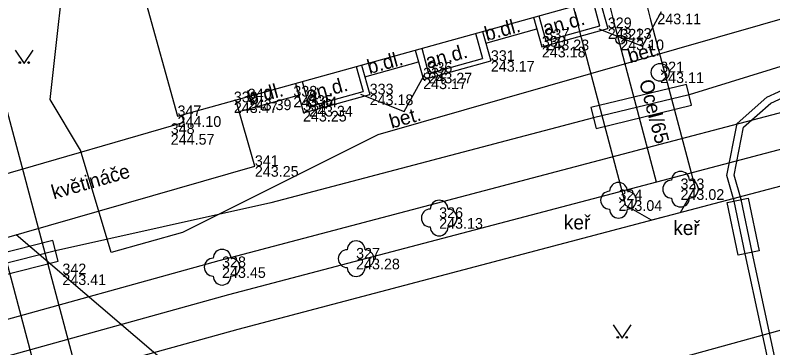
# Model space of a CAD drawing. Extents: x -599432 to -598680, y -1159407 to -1158632.
# Drawn here: x -599127.27 to -599106.02, y -1158908.05 to -1158898.71 of the extents above; entities that cross this region are included whole.
import ezdxf

# ---------------------------------------------------------------- set-up
doc = ezdxf.new("R2010")
doc.units = 0
for name, color, linetype in [('0004 VY - Body podrobné', 7, 'Continuous'), ('0005 VY - Body podrobné - čísla', 7, 'Continuous'), ('0006 VY - Body podrobné - výšky', 7, 'Continuous'), ('0007 ZA - Budova - zděná', 7, 'Continuous'), ('0025 ZA - Opěrná zeď', 7, 'Continuous'), ('0030 ZA - Chodník', 7, 'Continuous'), ('0031 ZA - Ostatní rozhraní', 7, 'Continuous'), ('0032 TE - Popis povrchu', 7, 'Continuous'), ('0034 ZA - Kultury - značky', 7, 'Continuous'), ('0035 ZA - Strom - značka', 7, 'Continuous'), ('0036 TE - Strom - popis', 7, 'Continuous'), ('0074 TE - Vysvětlivky', 7, 'Continuous'), ('0075 ZA - BVK - kanalizace - buňky', 7, 'Continuous'), ('0092 ZA - RWE - plynovod - buňky', 7, 'Continuous'), ('0116 PV - budova převzatá z mapy', 7, 'Continuous'), ('0254 PV - TB - horkovod - vedení', 7, 'Continuous'), ('0255 PV - TB - horkovod - okraj', 7, 'Continuous'), ('0264 PV - TB - parovod mimo provoz', 7, 'Continuous'), ('0301 PV - RWE - popis', 7, 'Continuous'), ('0302 PV - RWE - NTL', 7, 'Continuous'), ('0303 PV - RWE - NTL přípojka', 7, 'Continuous'), ('0308 PV - RWE - ochranné pásmo', 7, 'Continuous'), ('0354 PV - EON - VN', 7, 'Continuous'), ('0367 PV - EON - VN chránička', 7, 'Continuous'), ('0454 PV - PODA -  vedeni budoucnost', 7, 'Continuous'), ('0552 PV - NETBOX - vedení', 7, 'Continuous'), ('0553 PV - NETBOX - chranička', 7, 'Continuous')]:
    doc.layers.add(name, color=color, linetype=linetype)

msp = doc.modelspace()

# ---------------------------------------------------------------- linework, layer by layer
at = {"layer": '0004 VY - Body podrobné'}
for p, q in [((-599110.65, -1158899.08), (-599110.65, -1158899.08)), ((-599112.4, -1158899.4), (-599112.4, -1158899.4)), ((-599110.3, -1158899.4), (-599110.3, -1158899.4)), ((-599112.5, -1158899.6), (-599112.5, -1158899.6)), ((-599113.93, -1158900), (-599113.93, -1158900)), ((-599115.68, -1158900.33), (-599115.68, -1158900.33)), ((-599109.18, -1158900.32), (-599109.18, -1158900.32)), ((-599115.83, -1158900.49), (-599115.83, -1158900.49)), ((-599119.47, -1158901), (-599119.47, -1158901)), ((-599117.33, -1158900.94), (-599117.33, -1158900.94)), ((-599121.14, -1158901.16), (-599121.14, -1158901.16)), ((-599120.75, -1158901.08), (-599120.75, -1158901.08)), ((-599119.2, -1158901.4), (-599119.2, -1158901.4)), ((-599119.03, -1158901.26), (-599119.03, -1158901.26)), ((-599122.72, -1158901.55), (-599122.72, -1158901.55)), ((-599122.91, -1158902.05), (-599122.91, -1158902.05)), ((-599120.55, -1158902.95), (-599120.55, -1158902.95)), ((-599108.61, -1158903.6), (-599108.61, -1158903.6)), ((-599110.35, -1158903.91), (-599110.35, -1158903.91)), ((-599115.38, -1158904.41), (-599115.38, -1158904.41)), ((-599117.71, -1158905.55), (-599117.71, -1158905.55)), ((-599121.47, -1158905.79), (-599121.47, -1158905.79)), ((-599125.95, -1158905.99), (-599125.95, -1158905.99))]:
    msp.add_line(p, q, dxfattribs=at)
at = {"layer": '0007 ZA - Budova - zděná'}
msp.add_line((-599122.72, -1158901.55), (-599062.29, -1158884.74), dxfattribs=at)
at = {"layer": '0025 ZA - Opěrná zeď'}
for p, q in [((-599120.55, -1158902.95), (-599121.085, -1158901.095)), ((-599122.601, -1158901.517), (-599122.539, -1158901.732)), ((-599122.539, -1158901.732), (-599129.527, -1158903.746)), ((-599129.05, -1158905.4), (-599120.55, -1158902.95))]:
    msp.add_line(p, q, dxfattribs=at)
at = {"layer": '0030 ZA - Chodník'}
msp.add_line((-599116.59, -1158913.97), (-599127.25, -1158904.881), dxfattribs=at)
at = {"layer": '0031 ZA - Ostatní rozhraní'}
for p, q in [((-599110.879, -1158898.256), (-599110.649, -1158899.085)), ((-599111.074, -1158898.31), (-599110.878, -1158899.014)), ((-599112.731, -1158898.771), (-599112.5, -1158899.6)), ((-599112.586, -1158898.731), (-599112.39, -1158899.434)), ((-599114.07, -1158899.497), (-599112.639, -1158899.099)), ((-599112.5, -1158899.6), (-599110.649, -1158899.085)), ((-599112.39, -1158899.437), (-599110.877, -1158899.016)), ((-599114.358, -1158899.224), (-599114.162, -1158899.927)), ((-599114.161, -1158899.169), (-599113.931, -1158899.998)), ((-599116.051, -1158899.695), (-599115.821, -1158900.524)), ((-599115.871, -1158899.645), (-599115.675, -1158900.348)), ((-599115.674, -1158900.35), (-599114.162, -1158899.93)), ((-599117.708, -1158900.156), (-599117.512, -1158900.859)), ((-599117.56, -1158900.115), (-599117.329, -1158900.943)), ((-599117.469, -1158900.442), (-599115.96, -1158900.022)), ((-599115.821, -1158900.524), (-599113.931, -1158899.998)), ((-599119.22, -1158900.576), (-599119.024, -1158901.282)), ((-599119.414, -1158900.63), (-599119.184, -1158901.459)), ((-599120.991, -1158901.422), (-599119.323, -1158900.958)), ((-599119.184, -1158901.459), (-599117.329, -1158900.943)), ((-599119.024, -1158901.282), (-599117.511, -1158900.861))]:
    msp.add_line(p, q, dxfattribs=at)
at = {"layer": '0032 TE - Popis povrchu'}
for p, q in [((-599109.68, -1158899.585), (-599109.146, -1158898.614)), ((-599110.899, -1158899.097), (-599109.68, -1158899.585)), ((-599116.366, -1158901.421), (-599115.768, -1158900.335)), ((-599117.584, -1158900.933), (-599116.366, -1158901.421))]:
    msp.add_line(p, q, dxfattribs=at)
at = {"layer": '0034 ZA - Kultury - značky'}
for points in [[(-599127.271, -1158899.696), (-599127.021, -1158900.071), (-599126.771, -1158899.696)], [(-599110.495, -1158907.41), (-599110.245, -1158907.785), (-599109.995, -1158907.41)]]:
    msp.add_lwpolyline(points, dxfattribs=at)
for centre in [(-599127.146, -1158900.046), (-599126.896, -1158900.046), (-599110.37, -1158907.76), (-599110.12, -1158907.76)]:
    msp.add_circle(centre, 0.025, dxfattribs=at)
at = {"layer": '0035 ZA - Strom - značka'}
for centre in [(-599108.61, -1158903.6), (-599110.35, -1158903.91), (-599115.38, -1158904.41), (-599117.71, -1158905.55), (-599121.47, -1158905.79)]:
    msp.add_circle(centre, 0.00025, dxfattribs=at)
for centre, start, end in [((-599108.61, -1158903.35), 0, 180), ((-599108.86, -1158903.6), 90, 270), ((-599108.36, -1158903.6), 270, 90), ((-599110.35, -1158903.66), 0, 180), ((-599110.6, -1158903.91), 90, 270), ((-599110.1, -1158903.91), 270, 90), ((-599115.38, -1158904.16), 0, 180), ((-599108.61, -1158903.85), 180, 360), ((-599115.63, -1158904.41), 90, 270), ((-599115.13, -1158904.41), 270, 90), ((-599110.35, -1158904.16), 180, 360), ((-599115.38, -1158904.66), 180, 360), ((-599117.71, -1158905.3), 0, 180), ((-599121.47, -1158905.54), 0, 180), ((-599117.96, -1158905.55), 90, 270), ((-599117.46, -1158905.55), 270, 90), ((-599121.72, -1158905.79), 90, 270), ((-599121.22, -1158905.79), 270, 90), ((-599117.71, -1158905.8), 180, 360), ((-599121.47, -1158906.04), 180, 360)]:
    msp.add_arc(centre, 0.25, start, end, dxfattribs=at)
at = {"layer": '0075 ZA - BVK - kanalizace - buňky'}
msp.add_circle((-599109.18, -1158900.32), 0.25, dxfattribs=at)
at = {"layer": '0092 ZA - RWE - plynovod - buňky'}
msp.add_circle((-599110.3, -1158899.4), 0.125, dxfattribs=at)
at = {"layer": '0116 PV - budova převzatá z mapy'}
msp.add_line((-599126.36, -1158888.49), (-599122.72, -1158901.55), dxfattribs=at)
at = {"layer": '0254 PV - TB - horkovod - vedení'}
msp.add_line((-599130.737, -1158893.547), (-599118.2, -1158940.655), dxfattribs=at)
at = {"layer": '0255 PV - TB - horkovod - okraj'}
msp.add_line((-599129.678, -1158893.249), (-599117.137, -1158940.372), dxfattribs=at)
at = {"layer": '0264 PV - TB - parovod mimo provoz'}
msp.add_line((-599074.078, -1158898.846), (-599160.39, -1158922.56), dxfattribs=at)
at = {"layer": '0302 PV - RWE - NTL'}
msp.add_lwpolyline([(-599042.76, -1158885.49), (-599068.42, -1158892.17), (-599094.54, -1158899.36), (-599103.01, -1158901.75), (-599109.28, -1158903.4), (-599121.29, -1158906.57), (-599128.03, -1158908.44), (-599139.52, -1158911.687), (-599140.38, -1158911.93), (-599166.16, -1158919.18), (-599194.33, -1158927.1), (-599199.24, -1158928.46), (-599225.65, -1158935.9)], dxfattribs=at)
at = {"layer": '0303 PV - RWE - NTL přípojka'}
msp.add_lwpolyline([(-599109.28, -1158903.4), (-599110.42, -1158899.1), (-599110.66, -1158898.15)], dxfattribs=at)
at = {"layer": '0308 PV - RWE - ochranné pásmo'}
for points in [[(-599166.431, -1158918.217), (-599140.651, -1158910.968), (-599139.792, -1158910.725), (-599128.3, -1158907.477), (-599121.551, -1158905.605), (-599109.535, -1158902.433), (-599103.273, -1158900.785), (-599094.808, -1158898.397), (-599068.679, -1158891.204), (-599043.012, -1158884.522)], [(-599042.508, -1158886.458), (-599068.161, -1158893.136), (-599094.272, -1158900.323), (-599102.747, -1158902.715), (-599109.025, -1158904.367), (-599121.029, -1158907.535), (-599127.76, -1158909.403), (-599139.248, -1158912.649), (-599140.109, -1158912.892), (-599165.889, -1158920.143)]]:
    msp.add_lwpolyline(points, dxfattribs=at)
msp.add_lwpolyline([(-599110.141, -1158904.057), (-599110.247, -1158903.656), (-599111.388, -1158899.351), (-599111.63, -1158898.395), (-599111.731, -1158897.993), (-599111.306, -1158897.281), (-599110.905, -1158897.18), (-599110.503, -1158897.079), (-599109.791, -1158897.504), (-599109.69, -1158897.905), (-599109.452, -1158898.849), (-599108.313, -1158903.144), (-599108.207, -1158903.544), (-599108.623, -1158904.261), (-599109.024, -1158904.367), (-599109.424, -1158904.473)], close=True, dxfattribs=at)
at = {"layer": '0354 PV - EON - VN'}
for points in [[(-599100.02, -1158930.068), (-599101.253, -1158923.926), (-599102.806, -1158918.536), (-599103.846, -1158916.105), (-599105.285, -1158911.524), (-599105.454, -1158911.165), (-599105.752, -1158909.781), (-599105.72, -1158909.453), (-599106.602, -1158905.369), (-599106.913, -1158903.886), (-599107.107, -1158903.206), (-599106.839, -1158901.863), (-599106.075, -1158901.185), (-599105.137, -1158900.755), (-599099.225, -1158899.297), (-599095.622, -1158898.316), (-599094.203, -1158897.866), (-599092.546, -1158897.477), (-599083.302, -1158895.086), (-599074.947, -1158892.385), (-599069.734, -1158890.453), (-599068.354, -1158889.893), (-599062.365, -1158887.674)], [(-599145.539, -1158921.274), (-599140.537, -1158919.624), (-599136.405, -1158918.643), (-599130.705, -1158917.073), (-599126.184, -1158915.983), (-599122.341, -1158915.002), (-599120.4, -1158914.682), (-599115.645, -1158913.543), (-599111.287, -1158912.334), (-599109.596, -1158911.863), (-599106.311, -1158911.019), (-599105.916, -1158909.495), (-599106.798, -1158905.411), (-599107.107, -1158903.934), (-599107.313, -1158903.214), (-599107.021, -1158901.757), (-599106.185, -1158901.015), (-599105.203, -1158900.565)]]:
    msp.add_lwpolyline(points, dxfattribs=at)
at = {"layer": '0367 PV - EON - VN chránička'}
for p, q in [((-599107.304, -1158903.972), (-599106.716, -1158903.848)), ((-599106.994, -1158905.452), (-599107.304, -1158903.972)), ((-599106.716, -1158903.848), (-599106.406, -1158905.328)), ((-599106.406, -1158905.328), (-599106.994, -1158905.452))]:
    msp.add_line(p, q, dxfattribs=at)
at = {"layer": '0454 PV - PODA -  vedeni budoucnost'}
msp.add_lwpolyline([(-599105.17, -1158898.649), (-599117.1, -1158902.075), (-599122.583, -1158904.816), (-599124.582, -1158905.375), (-599125.445, -1158902.506), (-599126.295, -1158901.085), (-599125.775, -1158896.452), (-599128.034, -1158888.659), (-599130.281, -1158879.673), (-599132.87, -1158880.447), (-599147.378, -1158884.773)], dxfattribs=at)
at = {"layer": '0552 PV - NETBOX - vedení'}
msp.add_lwpolyline([(-599102.74, -1158899.21), (-599108.37, -1158900.95), (-599108.37, -1158900.95), (-599111.05, -1158901.6), (-599111.05, -1158901.6), (-599120.1, -1158903.98), (-599120.1, -1158903.98), (-599126.14, -1158905.33), (-599126.14, -1158905.33), (-599129.83, -1158906.27), (-599130.84, -1158906.53), (-599131.75, -1158903.39), (-599131.75, -1158903.39), (-599133.77, -1158895.45)], dxfattribs=at)
at = {"layer": '0553 PV - NETBOX - chranička'}
for points in [[(-599108.441, -1158900.658), (-599111.121, -1158901.308), (-599110.979, -1158901.892), (-599108.299, -1158901.242), (-599108.441, -1158900.658)], [(-599126.214, -1158905.039), (-599129.904, -1158905.979), (-599129.756, -1158906.561), (-599126.066, -1158905.621), (-599126.214, -1158905.039)]]:
    msp.add_lwpolyline(points, dxfattribs=at)

# ---------------------------------------------------------------- texts
at = {"layer": '0005 VY - Body podrobné - čísla'}
for s, p in [('329', (-599110.65, -1158899.08)), ('337', (-599112.4, -1158899.4)), ('322', (-599110.3, -1158899.4)), ('330', (-599112.5, -1158899.6)), ('331', (-599113.93, -1158900)), ('332', (-599115.83, -1158900.49)), ('336', (-599115.68, -1158900.33)), ('321', (-599109.18, -1158900.32)), ('340', (-599120.75, -1158901.08)), ('338', (-599119.47, -1158901)), ('333', (-599117.33, -1158900.94)), ('339', (-599121.14, -1158901.16)), ('335', (-599119.03, -1158901.26)), ('347', (-599122.72, -1158901.55)), ('334', (-599119.2, -1158901.4)), ('348', (-599122.91, -1158902.05)), ('341', (-599120.55, -1158902.95)), ('323', (-599108.61, -1158903.6)), ('324', (-599110.35, -1158903.91)), ('326', (-599115.38, -1158904.41)), ('327', (-599117.71, -1158905.55)), ('328', (-599121.47, -1158905.79)), ('342', (-599125.95, -1158905.99))]:
    msp.add_text(s, height=0.3, dxfattribs=at).set_placement(p)
at = {"layer": '0006 VY - Body podrobné - výšky'}
for s, p in [('243.11', (-599109.26, -1158898.97)), ('243.13', (-599110.65, -1158899.38)), ('243.23', (-599112.4, -1158899.7)), ('243.10', (-599110.3, -1158899.7)), ('243.18', (-599112.5, -1158899.9)), ('243.17', (-599113.93, -1158900.3)), ('243.27', (-599115.68, -1158900.63)), ('243.11', (-599109.18, -1158900.62)), ('243.17', (-599115.83, -1158900.79)), ('243.34', (-599119.47, -1158901.3)), ('243.18', (-599117.33, -1158901.24)), ('243.47', (-599121.14, -1158901.46)), ('243.39', (-599120.75, -1158901.38)), ('243.25', (-599119.2, -1158901.7)), ('243.34', (-599119.03, -1158901.56)), ('244.10', (-599122.72, -1158901.85)), ('244.57', (-599122.91, -1158902.35)), ('243.25', (-599120.55, -1158903.25)), ('243.02', (-599108.61, -1158903.9)), ('243.04', (-599110.35, -1158904.21)), ('243.13', (-599115.38, -1158904.71)), ('243.28', (-599117.71, -1158905.85)), ('243.45', (-599121.47, -1158906.09)), ('243.41', (-599125.95, -1158906.29))]:
    msp.add_text(s, height=0.3, dxfattribs=at).set_placement(p)
at = {"layer": '0032 TE - Popis povrchu'}
for s, p in [('an.d.', (-599112.406, -1158899.29)), ('b.dl.', (-599114.044, -1158899.443)), ('an.d.', (-599115.699, -1158900.218)), ('bet.', (-599110.03, -1158900.066)), ('b.dl.', (-599117.336, -1158900.371)), ('an.d.', (-599119.056, -1158901.146)), ('b.dl.', (-599120.693, -1158901.25)), ('bet.', (-599116.716, -1158901.901))]:
    msp.add_text(s, height=0.4, rotation=15.5451, dxfattribs=at).set_placement(p)
at = {"layer": '0036 TE - Strom - popis'}
for p in [(-599111.883, -1158904.73), (-599108.813, -1158904.887)]:
    msp.add_text('keř', height=0.4, dxfattribs=at).set_placement(p)
at = {"layer": '0074 TE - Vysvětlivky'}
msp.add_text('květináče', height=0.4, rotation=16.0788, dxfattribs=at).set_placement((-599126.191, -1158903.888))
at = {"layer": '0301 PV - RWE - popis'}
msp.add_text('Ocel/65', height=0.4, rotation=284.8485, dxfattribs=at).set_placement((-599109.776, -1158900.576))

doc.saveas('drawing.dxf')
